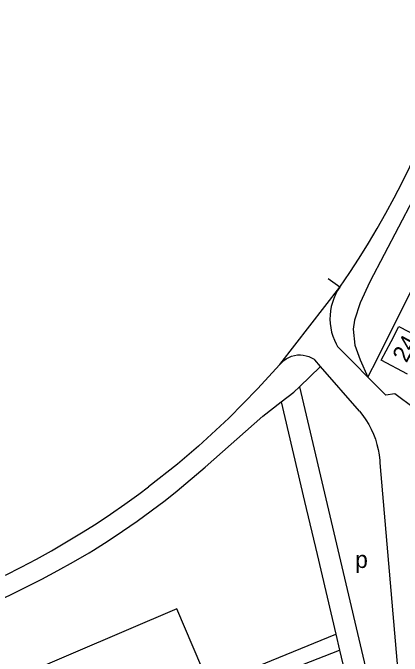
# Model space of a CAD drawing. Extents: x 162667 to 164645, y 379003 to 382150.
# Drawn here: x 163002.4 to 163094, y 380855.2 to 381006.6 of the extents above; entities that cross this region are included whole.
import ezdxf

# ---------------------------------------------------------------- set-up
doc = ezdxf.new("R2010")
doc.units = 0
for name, color, linetype in [('BLT_Basislijn', 7, 'Continuous'), ('BLT_Bebouwing', 7, 'Continuous'), ('BLT_Centroide', 7, 'Continuous'), ('BLT_Huisnummer', 7, 'Continuous'), ('BLT_Vlakafsluiter', 7, 'Continuous')]:
    doc.layers.add(name, color=color, linetype=linetype)

msp = doc.modelspace()

# ---------------------------------------------------------------- linework, layer by layer
at = {"layer": 'BLT_Basislijn'}
for p, q in [((163082.69, 380924.19), (163078.83, 380928.12)), ((163074.81, 380923.39), (163073.44, 380924.98)), ((163065.2, 380923.83), (163059.99, 380918.15)), ((163069.84, 380918.61), (163074.81, 380923.39)), ((163083.94, 380912.86), (163074.81, 380923.39)), ((163085.95, 380920.89), (163082.69, 380924.19)), ((163065.54, 380915.04), (163068.53, 380917.35)), ((163068.53, 380917.35), (163069.84, 380918.61)), ((163065.54, 380915.04), (163071.06, 380891.6)), ((163088.77, 380900.71), (163093.01, 380851.28)), ((163048.68, 380848.26), (163078.42, 380860.34)), ((163070.6, 380853.24), (163079.3, 380856.59))]:
    msp.add_line(p, q, dxfattribs=at)
for points in [[(163117.54, 381006.64), (163112.59, 380993.9), (163096.51, 380962.6), (163086.43, 380943.33)], [(163079.36, 380942.09), (163081.66, 380945.48), (163083.89, 380948.91), (163086.06, 380952.39), (163088.16, 380955.91), (163090.19, 380959.46), (163092.15, 380963.06), (163094.04, 380966.7), (163095.85, 380970.37), (163097.6, 380974.07), (163099.27, 380977.81), (163100.87, 380981.58), (163102.4, 380985.38), (163103.85, 380989.21), (163104.46, 380990.9)], [(163085.95, 380920.89), (163088.18, 380925.28), (163092.23, 380933.37), (163107.68, 380963.93)], [(163086.43, 380943.33), (163084.13, 380938.37), (163082.76, 380934.28), (163082.45, 380932.15), (163082.91, 380928.39), (163084.11, 380924.92), (163085.95, 380920.89)], [(163079.36, 380942.09), (163078.81, 380941.24), (163078.32, 380940.35), (163077.91, 380939.43), (163077.58, 380938.48), (163077.32, 380937.5), (163077.13, 380936.51), (163077.03, 380935.5), (163077.01, 380934.49), (163077.06, 380933.48), (163077.2, 380932.48), (163077.41, 380931.49), (163077.7, 380930.53), (163078.07, 380929.59), (163078.51, 380928.68), (163078.83, 380928.12)], [(163065.2, 380923.83), (163065.66, 380924.35), (163066.17, 380924.81), (163066.74, 380925.21), (163067.35, 380925.54), (163068, 380925.8), (163068.67, 380925.98), (163069.35, 380926.09), (163070.05, 380926.11), (163070.74, 380926.06), (163071.42, 380925.92), (163072.08, 380925.71), (163072.71, 380925.43), (163073.31, 380925.07), (163073.44, 380924.98)], [(163120.07, 380903.88), (163118.6, 380905.83), (163113.47, 380907.07), (163108.7, 380908.49), (163102.34, 380910.96), (163096.86, 380913.61), (163093.85, 380915.74), (163092.26, 380916.98), (163090.14, 380916.62), (163085.95, 380920.89)], [(163059.99, 380918.15), (163053.24, 380911.24), (163046.09, 380904.6), (163041.14, 380900.36), (163034.33, 380895.05)], [(163069.84, 380918.61), (163086.65, 380847.18), (163089.75, 380814.22)], [(163041.05, 380894.08), (163047.68, 380899.65), (163061.2, 380911.68), (163065.54, 380915.04)], [(163083.94, 380912.86), (163084.74, 380911.86), (163085.47, 380910.82), (163086.13, 380909.74), (163086.73, 380908.61), (163087.25, 380907.45), (163087.7, 380906.26), (163088.08, 380905.05), (163088.38, 380903.81), (163088.59, 380902.56), (163088.73, 380901.29), (163088.77, 380900.71)], [(163000.66, 380874.28), (163004.31, 380876.12), (163007.92, 380878.03), (163011.49, 380880.01), (163015.02, 380882.07), (163018.51, 380884.19), (163021.96, 380886.38), (163025.37, 380888.64), (163028.73, 380890.96), (163032.04, 380893.35), (163034.33, 380895.05)], [(163021.34, 380880.11), (163024.81, 380882.33), (163028.23, 380884.62), (163031.61, 380886.97), (163034.95, 380889.39), (163038.23, 380891.87), (163041.05, 380894.08)], [(163071.06, 380891.6), (163074, 380879.09)], [(162970.08, 380857.48), (162974.12, 380858.73), (162978.14, 380860.05), (162982.14, 380861.45), (162986.1, 380862.93), (162990.04, 380864.48), (162993.94, 380866.11), (162997.82, 380867.8), (163001.66, 380869.58), (163005.47, 380871.42), (163009.24, 380873.34), (163012.97, 380875.32), (163016.67, 380877.38), (163020.33, 380879.51), (163021.34, 380880.11)], [(163074, 380879.09), (163078.42, 380860.34)], [(163078.42, 380860.34), (163079.3, 380856.59)], [(163079.3, 380856.59), (163081.7, 380846.37), (163084.41, 380817.59)]]:
    msp.add_lwpolyline(points, dxfattribs=at)
at = {"layer": 'BLT_Bebouwing'}
for points in [[(163095.3, 380921.54), (163089.05, 380924.84), (163091.4, 380929.25), (163093.26, 380932.77), (163097.9, 380930.33), (163099.35, 380933.06), (163100.93, 380932.23)], [(163040.95, 380866.34), (163004.13, 380850.53)], [(163048.68, 380848.26), (163040.95, 380866.34)]]:
    msp.add_lwpolyline(points, dxfattribs=at)
at = {"layer": 'BLT_Vlakafsluiter'}
for p, q in [((163079.36, 380942.09), (163076.58, 380944.01)), ((163065.2, 380923.83), (163079.36, 380942.09))]:
    msp.add_line(p, q, dxfattribs=at)

# ---------------------------------------------------------------- texts
at = {"layer": 'BLT_Centroide'}
msp.add_text('p', height=4, dxfattribs=at).set_placement((163082.96, 380875.95))
at = {"layer": 'BLT_Huisnummer'}
msp.add_text('24', height=4, rotation=62.1448, dxfattribs=at).set_placement((163095.03, 380924.08))

doc.saveas('drawing.dxf')
